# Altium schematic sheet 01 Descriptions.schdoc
size 400 x 277 mm; Device: default420x297; Symbol: default420x297; Name: default420x297; Size: "A3"; Id: /; File: 01 Descriptions; Sheet: /
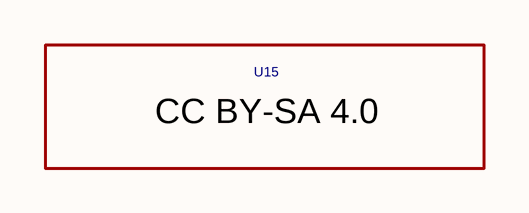
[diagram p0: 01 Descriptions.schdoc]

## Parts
U15  Misc_LOGO_CC_BY-SA_4.0  [Misc:LOGO_CC_BY-SA_4.0]  (value not drawn)

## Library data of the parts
U15 = Misc_LOGO_CC_BY-SA_4.0: UniqueId: 28995c53ef78d865; AddInBom: yes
